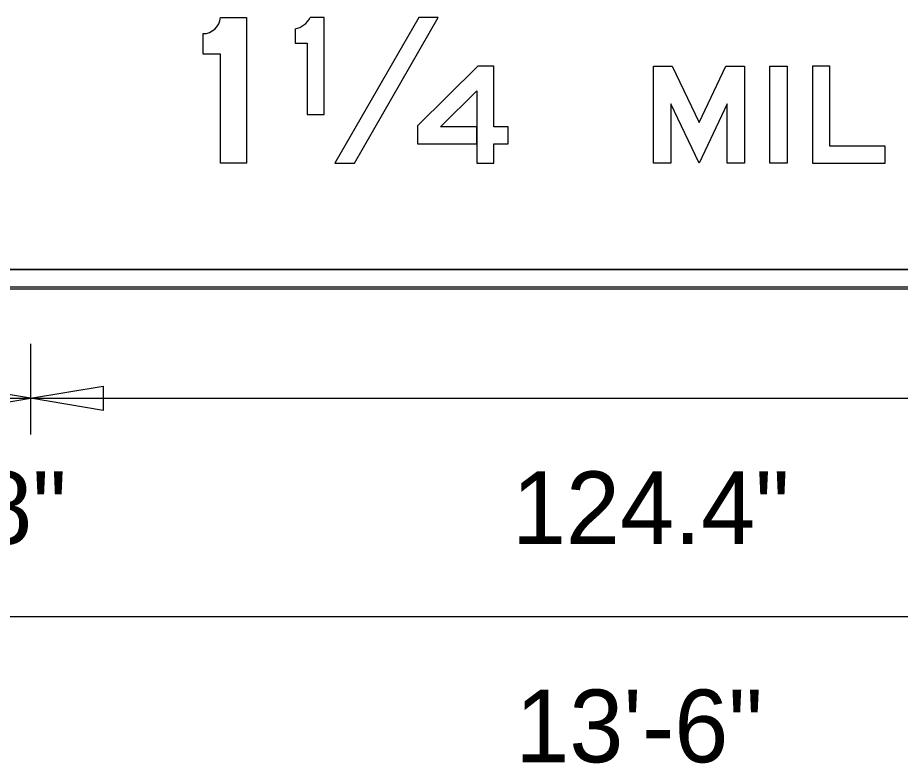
# Model space of a CAD drawing. Extents: x 1806251 to 1809821, y 414895 to 422886.
# Drawn here: x 1809676.959 to 1809677.87, y 415031.291 to 415032.06 of the extents above; entities that cross this region are included whole.
import ezdxf

# ---------------------------------------------------------------- set-up
doc = ezdxf.new("R2010")
doc.units = 0
for name, color, linetype in [('GSBWFILL', 7, 'Continuous'), ('GSCOLORFILL', 7, 'Continuous'), ('GSDIMS', 7, 'Continuous'), ('GSOUTLINE', 7, 'Continuous')]:
    doc.layers.add(name, color=color, linetype=linetype)

msp = doc.modelspace()

# ---------------------------------------------------------------- linework, layer by layer
at = {"layer": 'GSBWFILL'}
for p, q in [((1809677.24534, 415032.04872), (1809677.24534, 415032.03414)), ((1809678.28509, 415031.80057), (1809676.90529, 415031.80057)), ((1809676.90529, 415031.78057), (1809678.28509, 415031.78057))]:
    msp.add_line(p, q, dxfattribs=at)
for points in [[(1809677.16834, 415032.06039), (1809677.19534, 415032.06039), (1809677.19534, 415031.91039)], [(1809677.24534, 415032.03414), (1809677.25784, 415032.03414), (1809677.25784, 415031.96039), (1809677.27534, 415031.96039), (1809677.27534, 415032.06039), (1809677.26098, 415032.06039)], [(1809677.19534, 415031.91039), (1809677.16834, 415031.91039), (1809677.16834, 415032.02289), (1809677.15034, 415032.02289), (1809677.15034, 415032.04389)]]:
    msp.add_lwpolyline(points, dxfattribs=at)
for points in [[(1809677.28626, 415031.91039), (1809677.30647, 415031.91039), (1809677.39307, 415032.06039), (1809677.37286, 415032.06039)], [(1809677.4505, 415031.93036), (1809677.46509, 415031.93036), (1809677.46509, 415031.94786), (1809677.4505, 415031.94786), (1809677.4505, 415032.01039), (1809677.43386, 415032.01039), (1809677.37159, 415031.94888), (1809677.37159, 415031.93036), (1809677.43299, 415031.93036), (1809677.43299, 415031.94786), (1809677.39546, 415031.94786), (1809677.433, 415031.98494), (1809677.433, 415031.91039), (1809677.4505, 415031.91039)], [(1809677.66209, 415031.95231), (1809677.6897, 415032.01039), (1809677.70909, 415032.01039), (1809677.70909, 415031.91039), (1809677.69109, 415031.91039), (1809677.69109, 415031.97139), (1809677.66209, 415031.91039), (1809677.63309, 415031.97139), (1809677.63309, 415031.91039), (1809677.61509, 415031.91039), (1809677.61509, 415032.01039), (1809677.63448, 415032.01039)], [(1809677.73509, 415031.91039), (1809677.73509, 415032.01039), (1809677.75309, 415032.01039), (1809677.75309, 415031.91039)], [(1809677.85409, 415031.91039), (1809677.85409, 415031.92789), (1809677.79709, 415031.92789), (1809677.79709, 415032.01039), (1809677.77909, 415032.01039), (1809677.77909, 415031.91039)]]:
    msp.add_lwpolyline(points, close=True, dxfattribs=at)
msp.add_arc((1809677.24015, 415032.07201), 0.02386, 282.57163, 330.86344, dxfattribs=at)
msp.add_ellipse((1809677.15034, 415032.06196), major_axis=(0, 0.01807), ratio=0.999998, start_param=3.141593, end_param=4.625487, dxfattribs=at)
at = {"layer": 'GSCOLORFILL'}
for p, q in [((1809677.24534, 415032.04872), (1809677.24534, 415032.03414)), ((1809678.28509, 415031.80057), (1809676.90529, 415031.80057)), ((1809676.90509, 415031.78057), (1809678.28509, 415031.78057)), ((1809678.28509, 415031.78257), (1809676.90511, 415031.78257)), ((1809676.90511, 415031.78057), (1809678.28509, 415031.78057)), ((1809676.90529, 415031.78057), (1809678.28509, 415031.78057))]:
    msp.add_line(p, q, dxfattribs=at)
for points in [[(1809677.16834, 415032.06039), (1809677.19534, 415032.06039), (1809677.19534, 415031.91039)], [(1809677.24534, 415032.03414), (1809677.25784, 415032.03414), (1809677.25784, 415031.96039), (1809677.27534, 415031.96039), (1809677.27534, 415032.06039), (1809677.26098, 415032.06039)], [(1809677.19534, 415031.91039), (1809677.16834, 415031.91039), (1809677.16834, 415032.02289), (1809677.15034, 415032.02289), (1809677.15034, 415032.04389)]]:
    msp.add_lwpolyline(points, dxfattribs=at)
for points in [[(1809677.28626, 415031.91039), (1809677.30647, 415031.91039), (1809677.39307, 415032.06039), (1809677.37286, 415032.06039)], [(1809677.4505, 415031.93036), (1809677.46509, 415031.93036), (1809677.46509, 415031.94786), (1809677.4505, 415031.94786), (1809677.4505, 415032.01039), (1809677.43386, 415032.01039), (1809677.37159, 415031.94888), (1809677.37159, 415031.93036), (1809677.43299, 415031.93036), (1809677.43299, 415031.94786), (1809677.39546, 415031.94786), (1809677.433, 415031.98494), (1809677.433, 415031.91039), (1809677.4505, 415031.91039)], [(1809677.66209, 415031.95231), (1809677.6897, 415032.01039), (1809677.70909, 415032.01039), (1809677.70909, 415031.91039), (1809677.69109, 415031.91039), (1809677.69109, 415031.97139), (1809677.66209, 415031.91039), (1809677.63309, 415031.97139), (1809677.63309, 415031.91039), (1809677.61509, 415031.91039), (1809677.61509, 415032.01039), (1809677.63448, 415032.01039)], [(1809677.73509, 415031.91039), (1809677.73509, 415032.01039), (1809677.75309, 415032.01039), (1809677.75309, 415031.91039)], [(1809677.85409, 415031.91039), (1809677.85409, 415031.92789), (1809677.79709, 415031.92789), (1809677.79709, 415032.01039), (1809677.77909, 415032.01039), (1809677.77909, 415031.91039)]]:
    msp.add_lwpolyline(points, close=True, dxfattribs=at)
msp.add_arc((1809677.24015, 415032.07201), 0.02386, 282.57163, 330.86344, dxfattribs=at)
msp.add_ellipse((1809677.15034, 415032.06196), major_axis=(0, 0.01807), ratio=0.999998, start_param=3.141593, end_param=4.625487, dxfattribs=at)
at = {"layer": 'GSDIMS'}
for p, q in [((1809676.97249, 415031.72414), (1809676.97249, 415031.63039)), ((1809676.97249, 415031.72414), (1809676.97249, 415031.63039)), ((1809676.78446, 415031.66789), (1809676.97249, 415031.66789)), ((1809676.97249, 415031.66789), (1809678.21646, 415031.66789)), ((1809676.78446, 415031.44289), (1809678.40546, 415031.44289))]:
    msp.add_line(p, q, dxfattribs=at)
for points in [[(1809676.97249, 415031.66789), (1809676.89749, 415031.68039), (1809676.89749, 415031.65539)], [(1809676.97249, 415031.66789), (1809677.04749, 415031.68039), (1809677.04749, 415031.65539)]]:
    msp.add_lwpolyline(points, close=True, dxfattribs=at)
at = {"layer": 'GSOUTLINE'}
for p, q in [((1809677.24534, 415032.04872), (1809677.24534, 415032.03414)), ((1809676.90509, 415031.80057), (1809678.28509, 415031.80057)), ((1809676.90509, 415031.78057), (1809678.28509, 415031.78057))]:
    msp.add_line(p, q, dxfattribs=at)
for points in [[(1809677.16834, 415032.06039), (1809677.19534, 415032.06039), (1809677.19534, 415031.91039)], [(1809677.24534, 415032.03414), (1809677.25784, 415032.03414), (1809677.25784, 415031.96039), (1809677.27534, 415031.96039), (1809677.27534, 415032.06039), (1809677.26098, 415032.06039)], [(1809677.19534, 415031.91039), (1809677.16834, 415031.91039), (1809677.16834, 415032.02289), (1809677.15034, 415032.02289), (1809677.15034, 415032.04389)]]:
    msp.add_lwpolyline(points, dxfattribs=at)
for points in [[(1809677.28626, 415031.91039), (1809677.30647, 415031.91039), (1809677.39307, 415032.06039), (1809677.37286, 415032.06039)], [(1809677.4505, 415031.91039), (1809677.4505, 415031.93036), (1809677.46509, 415031.93036), (1809677.46509, 415031.94786), (1809677.4505, 415031.94786), (1809677.4505, 415032.01039), (1809677.43386, 415032.01039), (1809677.37159, 415031.94888), (1809677.37159, 415031.93036), (1809677.433, 415031.93036), (1809677.433, 415031.91039)], [(1809677.66209, 415031.95231), (1809677.6897, 415032.01039), (1809677.70909, 415032.01039), (1809677.70909, 415031.91039), (1809677.69109, 415031.91039), (1809677.69109, 415031.97139), (1809677.66209, 415031.91039), (1809677.63309, 415031.97139), (1809677.63309, 415031.91039), (1809677.61509, 415031.91039), (1809677.61509, 415032.01039), (1809677.63448, 415032.01039)], [(1809677.73509, 415031.91039), (1809677.73509, 415032.01039), (1809677.75309, 415032.01039), (1809677.75309, 415031.91039)], [(1809677.85409, 415031.91039), (1809677.85409, 415031.92789), (1809677.79709, 415031.92789), (1809677.79709, 415032.01039), (1809677.77909, 415032.01039), (1809677.77909, 415031.91039)], [(1809677.433, 415031.94786), (1809677.39546, 415031.94786), (1809677.433, 415031.98494)]]:
    msp.add_lwpolyline(points, close=True, dxfattribs=at)
msp.add_arc((1809677.24015, 415032.07201), 0.02386, 282.57163, 330.86344, dxfattribs=at)
msp.add_ellipse((1809677.15034, 415032.06196), major_axis=(0, 0.01807), ratio=0.999998, start_param=3.141593, end_param=4.625487, dxfattribs=at)

# ---------------------------------------------------------------- texts
at = {"layer": 'GSDIMS'}
for s, p in [('18.8"', (1809676.77899, 415031.51739)), ('124.4"', (1809677.46899, 415031.51739)), ('13\'-6"', (1809677.47246, 415031.29239))]:
    msp.add_text(s, height=0.075, dxfattribs=at).set_placement(p)

doc.saveas('drawing.dxf')
